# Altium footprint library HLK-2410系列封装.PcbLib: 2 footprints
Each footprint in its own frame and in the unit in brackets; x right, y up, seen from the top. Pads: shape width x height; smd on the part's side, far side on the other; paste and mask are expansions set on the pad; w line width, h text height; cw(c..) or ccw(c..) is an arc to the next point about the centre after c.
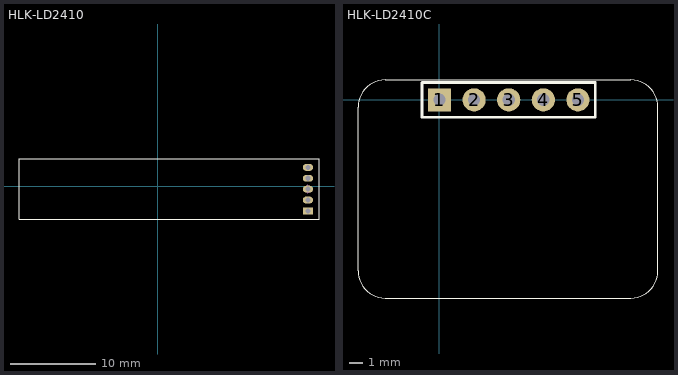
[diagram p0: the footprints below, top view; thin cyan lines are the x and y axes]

## HLK-LD2410 [mm] "海凌科24G雷达模块"
pads (5):
  rect 1.2x0.8 hole 0.6: 1(17.506,-2.87)
  oval 1.2x0.8 hole 0.6: 2(17.506,-1.6) 3(17.506,-0.33) 4(17.506,0.94) 5(17.506,2.21)
Top Overlay:
  lines w0.1: -16.204,-3.81 18.796,-3.81 18.796,3.19 -16.204,3.19 -16.204,-3.81
Bottom Overlay:
  lines w0.254: 16.236,-3.124 16.744,-3.632 ; 16.236,-2.235 18.776,-2.235 ; 16.236,-0.965 18.706,-0.965 ; 16.306,0.305 18.776,0.305 ; 18.776,1.575 16.271,1.575 ; 16.271,1.575 16.271,1.575 ; 16.236,-3.632 18.776,-3.632 18.776,2.972 16.236,2.972 16.236,-3.632
Mechanical 15:
  circle w0.05: c17.506,-0.33 r0.35
  lines w0.05: 17.006,-0.33 18.006,-0.33 ; 17.506,-0.83 17.506,0.17
3D body "HLK-LD2410-V1.1.step": height 1.68, standoff -7.62, extent -16.284,-4.357 18.886,3.643

## HLK-LD2410C [mm] "海凌科24G雷达模块"
pads (5):
  rect 1.7x1.7 hole 0.9: 1(0,0)
  round 1.7 hole 0.9: 2(2.54,0) 3(5.08,0) 4(7.62,0) 5(10.16,0)
Top Overlay:
  lines w0.025: -5.972,-12.536 ccw(c-3.972,-12.536) -3.972,-14.536 14.028,-14.536 ccw(c14.028,-12.536) 16.028,-12.536 16.028,-0.536 ccw(c14.028,-0.536) 14.028,1.464 -3.972,1.464 ccw(c-3.972,-0.536) -5.972,-0.536 -5.972,-12.536
  lines w0.2: -1.27,-1.27 11.43,-1.27 11.43,1.27 -1.27,1.27 -1.27,-1.27
3D body "HLK-LD2410C.step": height 2.01, standoff -9.49, extent -5.972,-14.536 16.028,1.464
